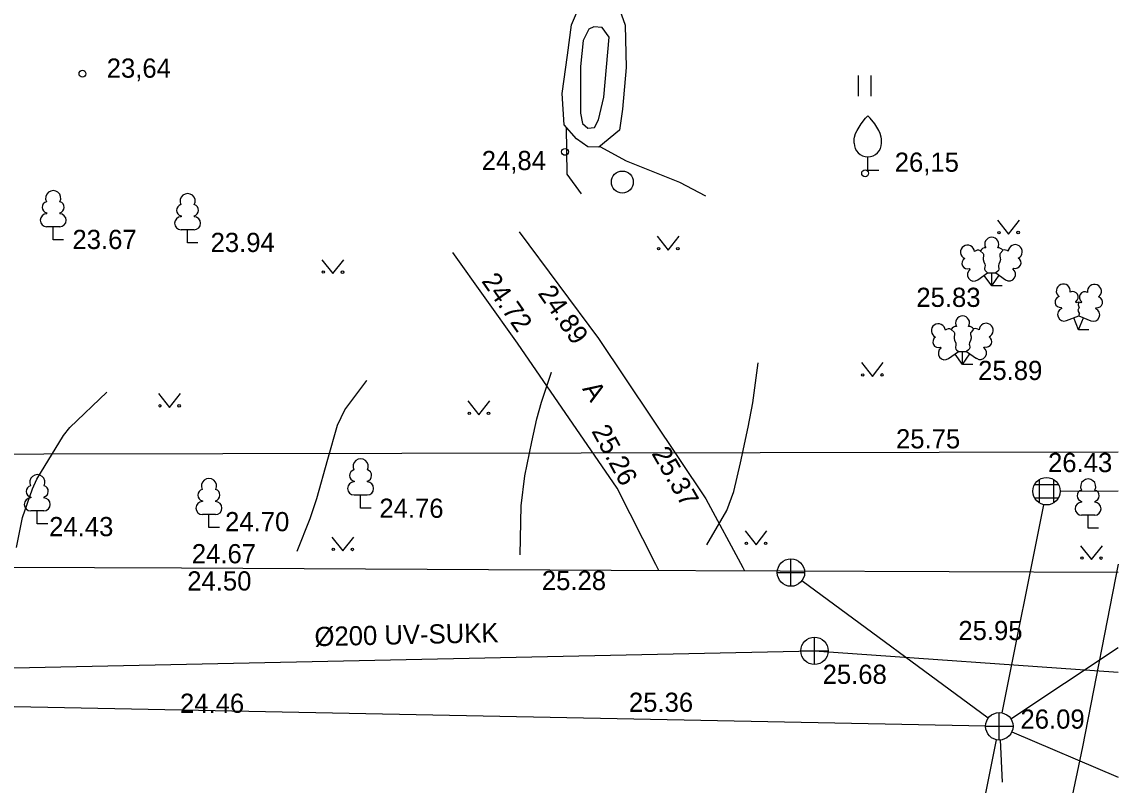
# Model space of a CAD drawing. Extents: x 714391 to 714584, y 6589993 to 6590151.
# Drawn here: x 714543.92 to 714583.92, y 6590093.39 to 6590121.23 of the extents above; entities that cross this region are included whole.
import ezdxf

# ---------------------------------------------------------------- set-up
doc = ezdxf.new("R2010")
doc.units = 0
for name, color, linetype in [('DKAEV', 7, 'Continuous'), ('HALJASTUS', 7, 'Continuous'), ('HOONE', 7, 'Continuous'), ('HORISONTAAL', 7, 'Continuous'), ('KKAEV', 7, 'Continuous'), ('KORGUS', 7, 'Continuous'), ('KTRASS', 7, 'Continuous'), ('PUU', 7, 'Continuous'), ('RELJEEF', 7, 'Continuous'), ('SKTRASS', 7, 'Continuous'), ('TEE', 7, 'Continuous'), ('TTRASS', 7, 'Continuous'), ('VTRASS', 7, 'Continuous')]:
    doc.layers.add(name, color=color, linetype=linetype)

msp = doc.modelspace()

# ---------------------------------------------------------------- linework, layer by layer
at = {"layer": 'DKAEV'}
for p, q in [((714581.058, 6590103.678), (714581.058, 6590104.544)), ((714581.558, 6590104.544), (714581.558, 6590103.678)), ((714580.875, 6590104.361), (714581.741, 6590104.361)), ((714581.741, 6590103.861), (714580.875, 6590103.861))]:
    msp.add_line(p, q, dxfattribs=at)
msp.add_circle((714581.308, 6590104.111), 0.5, dxfattribs=at)
at = {"layer": 'HALJASTUS'}
for p, q in [((714574.442, 6590119.281), (714574.442, 6590118.519)), ((714574.898, 6590119.281), (714574.898, 6590118.519)), ((714579.52, 6590113.998), (714579.925, 6590113.493)), ((714579.925, 6590113.493), (714580.32, 6590113.998)), ((714567.103, 6590113.411), (714567.508, 6590112.906)), ((714567.508, 6590112.906), (714567.903, 6590113.411)), ((714554.867, 6590112.553), (714555.272, 6590112.048)), ((714555.272, 6590112.048), (714555.667, 6590112.553)), ((714574.554, 6590108.805), (714574.959, 6590108.3)), ((714574.959, 6590108.3), (714575.354, 6590108.805)), ((714548.906, 6590107.676), (714549.311, 6590107.171)), ((714549.311, 6590107.171), (714549.706, 6590107.676)), ((714560.195, 6590107.406), (714560.6, 6590106.901)), ((714560.6, 6590106.901), (714560.995, 6590107.406)), ((714570.309, 6590102.664), (714570.714, 6590102.159)), ((714570.714, 6590102.159), (714571.109, 6590102.664)), ((714555.228, 6590102.439), (714555.633, 6590101.934)), ((714555.633, 6590101.934), (714556.028, 6590102.439)), ((714582.546, 6590102.123), (714582.951, 6590101.618)), ((714582.951, 6590101.618), (714583.346, 6590102.123))]:
    msp.add_line(p, q, dxfattribs=at)
for points in [[(714565.67, 6590121.87), (714565.94, 6590121.11), (714565.97, 6590119.57), (714565.84, 6590118.05), (714565.73, 6590117.28), (714564.97, 6590116.66), (714564.57, 6590116.68), (714564.16, 6590116.97), (714563.71, 6590117.48), (714563.64, 6590118.62), (714563.83, 6590120.02), (714563.98, 6590121.12), (714564.29, 6590121.86)], [(714564.343, 6590114.958), (714563.82, 6590115.68), (714563.79, 6590117.39)], [(714565.01, 6590116.69), (714565.97, 6590116.16), (714567.92, 6590115.39), (714568.862, 6590114.892)]]:
    msp.add_lwpolyline(points, dxfattribs=at)
for centre, radius in [((714565.83, 6590115.39), 0.4), ((714579.572, 6590113.548), 0.0428), ((714580.272, 6590113.548), 0.0452), ((714567.155, 6590112.961), 0.0428), ((714567.855, 6590112.961), 0.0452), ((714554.919, 6590112.103), 0.0428), ((714555.619, 6590112.103), 0.0452), ((714574.606, 6590108.356), 0.0428), ((714575.306, 6590108.356), 0.0452), ((714548.958, 6590107.227), 0.0428), ((714549.658, 6590107.227), 0.0452), ((714560.247, 6590106.956), 0.0428), ((714560.947, 6590106.956), 0.0452), ((714570.361, 6590102.215), 0.0428), ((714571.061, 6590102.215), 0.0452), ((714555.28, 6590101.989), 0.0428), ((714555.98, 6590101.989), 0.0452), ((714582.598, 6590101.673), 0.0428), ((714583.298, 6590101.673), 0.0452)]:
    msp.add_circle(centre, radius, dxfattribs=at)
at = {"layer": 'HOONE'}
for p, q in [((714581.808, 6590104.114), (714583.92, 6590104.125)), ((714579.685, 6590096.028), (714581.21, 6590103.621)), ((714580.047, 6590095.341), (714583.92, 6590093.681))]:
    msp.add_line(p, q, dxfattribs=at)
at = {"layer": 'HORISONTAAL'}
for points in [[(714568.917, 6590102.154), (714569.639, 6590103.411), (714569.639, 6590103.411), (714569.895, 6590104.108), (714569.895, 6590104.108), (714570.14, 6590105.146), (714570.14, 6590105.146), (714570.427, 6590106.452), (714570.427, 6590106.452), (714570.591, 6590107.34), (714570.591, 6590107.34), (714570.791, 6590108.791), (714570.791, 6590108.791)], [(714553.968, 6590101.924), (714554.438, 6590103.119), (714554.438, 6590103.119), (714554.685, 6590103.847), (714554.685, 6590103.847), (714555.084, 6590105.277), (714555.084, 6590105.277), (714555.435, 6590106.518), (714555.435, 6590106.518), (714555.701, 6590107.079), (714555.701, 6590107.079), (714556.507, 6590108.153), (714556.507, 6590108.153)], [(714562.098, 6590101.794), (714562.135, 6590103.58), (714562.135, 6590103.58), (714562.278, 6590104.674), (714562.278, 6590104.674), (714562.533, 6590105.919), (714562.533, 6590105.919), (714562.715, 6590106.756), (714562.715, 6590106.756), (714562.877, 6590107.355), (714562.877, 6590107.355), (714563.251, 6590108.454), (714563.251, 6590108.454)], [(714543.72, 6590102.062), (714543.949, 6590103.152), (714543.949, 6590103.152), (714544.314, 6590104.204), (714544.314, 6590104.204), (714544.467, 6590104.547), (714545.44, 6590106.141), (714545.44, 6590106.141), (714545.675, 6590106.435), (714547.022, 6590107.729), (714547.022, 6590107.729)]]:
    msp.add_lwpolyline(points, dxfattribs=at)
at = {"layer": 'KKAEV'}
for p, q in [((714571.984, 6590100.645), (714571.984, 6590101.645)), ((714571.484, 6590101.145), (714572.484, 6590101.145)), ((714572.844, 6590097.791), (714572.844, 6590098.791)), ((714572.344, 6590098.291), (714573.344, 6590098.291)), ((714579.587, 6590095.038), (714579.587, 6590096.038)), ((714579.087, 6590095.538), (714580.087, 6590095.538))]:
    msp.add_line(p, q, dxfattribs=at)
for centre in [(714571.984, 6590101.145), (714572.844, 6590098.291), (714579.587, 6590095.538)]:
    msp.add_circle(centre, 0.5, dxfattribs=at)
at = {"layer": 'KORGUS'}
for centre in [(714546.13, 6590119.34), (714563.74, 6590116.49), (714574.69, 6590115.71)]:
    msp.add_circle(centre, 0.125, dxfattribs=at)
at = {"layer": 'KTRASS'}
msp.add_lwpolyline([(714540.177, 6590097.597), (714572.844, 6590098.291), (714583.92, 6590097.517)], dxfattribs=at)
at = {"layer": 'PUU'}
for p, q in [((714574.79, 6590115.81), (714574.79, 6590116.31)), ((714575.19, 6590115.81), (714574.79, 6590115.81)), ((714544.823, 6590114.261), (714544.823, 6590114.231)), ((714545.303, 6590114.261), (714545.303, 6590114.231)), ((714549.727, 6590114.152), (714549.727, 6590114.122)), ((714550.207, 6590114.152), (714550.207, 6590114.122)), ((714545.303, 6590113.756), (714544.823, 6590113.756)), ((714545.063, 6590113.281), (714545.063, 6590113.756)), ((714545.443, 6590113.281), (714545.063, 6590113.281)), ((714550.207, 6590113.647), (714549.727, 6590113.647)), ((714549.967, 6590113.172), (714549.967, 6590113.647)), ((714550.347, 6590113.172), (714549.967, 6590113.172)), ((714578.524, 6590112.203), (714578.499, 6590112.238)), ((714578.799, 6590111.818), (714579.159, 6590112.073)), ((714579.159, 6590112.073), (714579.454, 6590112.073)), ((714579.309, 6590111.598), (714579.309, 6590112.073)), ((714579.454, 6590112.073), (714579.814, 6590111.828)), ((714580.084, 6590112.218), (714580.104, 6590112.253)), ((714579.309, 6590111.598), (714579.034, 6590111.983)), ((714579.309, 6590111.598), (714579.579, 6590111.988)), ((714579.689, 6590111.598), (714579.309, 6590111.598)), ((714582.393, 6590110.989), (714582.378, 6590111.024)), ((714582.578, 6590110.984), (714582.593, 6590111.024)), ((714581.863, 6590110.779), (714581.848, 6590110.819)), ((714582.038, 6590110.334), (714582.483, 6590110.509)), ((714582.483, 6590110.509), (714582.923, 6590110.329)), ((714583.103, 6590110.769), (714583.118, 6590110.809)), ((714582.478, 6590109.999), (714582.303, 6590110.439)), ((714582.478, 6590109.999), (714582.658, 6590110.439)), ((714582.858, 6590109.999), (714582.478, 6590109.999)), ((714577.46, 6590109.334), (714577.435, 6590109.369)), ((714579.02, 6590109.349), (714579.04, 6590109.384)), ((714577.735, 6590108.949), (714578.095, 6590109.204)), ((714578.245, 6590108.729), (714577.97, 6590109.114)), ((714578.095, 6590109.204), (714578.39, 6590109.204)), ((714578.245, 6590108.729), (714578.245, 6590109.204)), ((714578.245, 6590108.729), (714578.515, 6590109.119)), ((714578.39, 6590109.204), (714578.75, 6590108.959)), ((714578.625, 6590108.729), (714578.245, 6590108.729)), ((714556.042, 6590104.479), (714556.042, 6590104.449)), ((714556.522, 6590104.479), (714556.522, 6590104.449)), ((714544.243, 6590103.9), (714544.243, 6590103.87)), ((714544.723, 6590103.9), (714544.723, 6590103.87)), ((714550.506, 6590103.764), (714550.506, 6590103.734)), ((714550.986, 6590103.764), (714550.986, 6590103.734)), ((714556.522, 6590103.974), (714556.042, 6590103.974)), ((714556.282, 6590103.499), (714556.282, 6590103.974)), ((714582.589, 6590103.742), (714582.589, 6590103.712)), ((714583.069, 6590103.742), (714583.069, 6590103.712)), ((714544.723, 6590103.395), (714544.243, 6590103.395)), ((714544.483, 6590102.92), (714544.483, 6590103.395)), ((714556.662, 6590103.499), (714556.282, 6590103.499)), ((714544.863, 6590102.92), (714544.483, 6590102.92)), ((714550.986, 6590103.259), (714550.506, 6590103.259)), ((714550.746, 6590102.784), (714550.746, 6590103.259)), ((714583.069, 6590103.237), (714582.589, 6590103.237)), ((714582.829, 6590102.762), (714582.829, 6590103.237)), ((714551.126, 6590102.784), (714550.746, 6590102.784)), ((714583.209, 6590102.762), (714582.829, 6590102.762))]:
    msp.add_line(p, q, dxfattribs=at)
for points in [[(714574.29, 6590116.81), (714574.29, 6590116.96), (714574.3, 6590117.025), (714574.335, 6590117.155), (714574.395, 6590117.275), (714574.54, 6590117.51), (714574.7, 6590117.715), (714574.79, 6590117.81)], [(714575.29, 6590116.81), (714575.29, 6590116.96), (714575.28, 6590117.025), (714575.245, 6590117.155), (714575.185, 6590117.275), (714575.04, 6590117.51), (714574.88, 6590117.715), (714574.79, 6590117.81)], [(714578.894, 6590112.883), (714578.999, 6590112.783), (714579.014, 6590112.753), (714579.014, 6590112.698), (714578.999, 6590112.608), (714578.999, 6590112.563), (714579.019, 6590112.483), (714579.059, 6590112.393), (714579.069, 6590112.348), (714579.064, 6590112.303), (714579.049, 6590112.238), (714579.049, 6590112.208), (714579.069, 6590112.168), (714579.094, 6590112.138), (714579.159, 6590112.073)], [(714579.714, 6590112.898), (714579.619, 6590112.783), (714579.604, 6590112.753), (714579.604, 6590112.698), (714579.619, 6590112.608), (714579.624, 6590112.563), (714579.604, 6590112.483), (714579.564, 6590112.393), (714579.554, 6590112.348), (714579.559, 6590112.303), (714579.574, 6590112.238), (714579.574, 6590112.208), (714579.554, 6590112.168), (714579.529, 6590112.138), (714579.459, 6590112.073)], [(714582.483, 6590111.004), (714582.463, 6590110.929), (714582.463, 6590110.909), (714582.473, 6590110.879), (714582.493, 6590110.844), (714582.498, 6590110.824), (714582.483, 6590110.789), (714582.458, 6590110.739), (714582.453, 6590110.714), (714582.458, 6590110.699), (714582.468, 6590110.669), (714582.503, 6590110.609), (714582.508, 6590110.589), (714582.503, 6590110.569), (714582.488, 6590110.534), (714582.483, 6590110.509)], [(714577.83, 6590110.014), (714577.935, 6590109.914), (714577.95, 6590109.884), (714577.95, 6590109.829), (714577.935, 6590109.739), (714577.935, 6590109.694), (714577.955, 6590109.614), (714577.995, 6590109.524), (714578.005, 6590109.479), (714578, 6590109.434), (714577.985, 6590109.369), (714577.985, 6590109.339), (714578.005, 6590109.299), (714578.03, 6590109.269), (714578.095, 6590109.204)], [(714578.65, 6590110.029), (714578.555, 6590109.914), (714578.54, 6590109.884), (714578.54, 6590109.829), (714578.555, 6590109.739), (714578.56, 6590109.694), (714578.54, 6590109.614), (714578.5, 6590109.524), (714578.49, 6590109.479), (714578.495, 6590109.434), (714578.51, 6590109.369), (714578.51, 6590109.339), (714578.49, 6590109.299), (714578.465, 6590109.269), (714578.395, 6590109.204)]]:
    msp.add_lwpolyline(points, dxfattribs=at)
for centre, radius, start, end in [((714574.79, 6590116.81), 0.5, 180, 0), ((714545.063, 6590114.801), 0.277, 332.5799, 207.4201), ((714549.967, 6590114.692), 0.277, 332.5799, 207.4201), ((714544.873, 6590114.469), 0.212, 105.2441, 257.079), ((714545.253, 6590114.469), 0.212, 282.921, 74.7559), ((714549.777, 6590114.36), 0.212, 105.2441, 257.079), ((714550.157, 6590114.36), 0.212, 282.921, 74.7559), ((714544.826, 6590113.994), 0.237, 90, 270), ((714545.301, 6590113.994), 0.237, 270, 90), ((714549.729, 6590113.885), 0.237, 90, 270), ((714550.204, 6590113.885), 0.237, 270, 90), ((714579.309, 6590113.118), 0.256, 90.0013, 211.0159), ((714579.309, 6590113.118), 0.256, 328.9841, 89.9987), ((714578.426, 6590112.835), 0.256, 125.5389, 246.5536), ((714578.426, 6590112.835), 0.256, 4.5218, 125.5364), ((714578.812, 6590112.702), 0.202, 65.2382, 130.7412), ((714579.071, 6590112.786), 0.202, 84.7965, 150.2995), ((714579.546, 6590112.786), 0.202, 34.3857, 95.2035), ((714579.785, 6590112.711), 0.202, 50.3173, 111.1351), ((714580.169, 6590112.851), 0.256, 55.522, 176.5367), ((714580.169, 6590112.851), 0.256, 294.5049, 55.5195), ((714578.426, 6590112.426), 0.202, 120.3342, 291.9047), ((714580.177, 6590112.442), 0.202, 249.1538, 60.7243), ((714578.663, 6590112.012), 0.237, 125.5377, 305.5366), ((714579.947, 6590112.024), 0.237, 235.5219, 55.5208), ((714581.921, 6590111.413), 0.256, 350.4856, 111.5002), ((714581.921, 6590111.413), 0.256, 111.5027, 232.5173), ((714582.264, 6590111.191), 0.202, 305.1345, 116.705), ((714582.711, 6590111.187), 0.202, 62.412, 233.9825), ((714583.057, 6590111.404), 0.256, 67.6168, 188.6314), ((714583.057, 6590111.404), 0.256, 306.5997, 67.6143), ((714581.822, 6590111.017), 0.202, 106.2979, 277.8684), ((714582.482, 6590110.766), 0.237, 66.7655, 111.5015), ((714583.15, 6590111.007), 0.202, 261.2486, 72.8191), ((714578.245, 6590110.249), 0.256, 90.0013, 211.0159), ((714578.245, 6590110.249), 0.256, 328.9841, 89.9987), ((714581.952, 6590110.557), 0.237, 111.5014, 291.5004), ((714583.013, 6590110.549), 0.237, 247.6166, 67.6155), ((714577.362, 6590109.966), 0.256, 125.5389, 246.5536), ((714577.362, 6590109.966), 0.256, 4.5218, 125.5364), ((714578.007, 6590109.917), 0.202, 84.7965, 150.2995), ((714578.482, 6590109.917), 0.202, 34.3857, 95.2035), ((714579.105, 6590109.982), 0.256, 55.522, 176.5367), ((714579.105, 6590109.982), 0.256, 294.5049, 55.5195), ((714577.362, 6590109.557), 0.202, 120.3342, 291.9047), ((714577.748, 6590109.833), 0.202, 65.2382, 130.7412), ((714578.721, 6590109.842), 0.202, 50.3173, 111.1351), ((714579.113, 6590109.573), 0.202, 249.1538, 60.7243), ((714577.599, 6590109.143), 0.237, 125.5377, 305.5366), ((714578.883, 6590109.155), 0.237, 235.5219, 55.5208), ((714556.282, 6590105.019), 0.277, 332.5799, 207.4201), ((714556.092, 6590104.687), 0.212, 105.2441, 257.079), ((714556.472, 6590104.687), 0.212, 282.921, 74.7559), ((714544.483, 6590104.44), 0.277, 332.5799, 207.4201), ((714550.746, 6590104.304), 0.277, 332.5799, 207.4201), ((714582.829, 6590104.282), 0.277, 332.5799, 207.4201), ((714544.293, 6590104.107), 0.212, 105.2441, 257.079), ((714544.673, 6590104.107), 0.212, 282.921, 74.7559), ((714550.556, 6590103.971), 0.212, 105.2441, 257.079), ((714550.936, 6590103.971), 0.212, 282.921, 74.7559), ((714556.044, 6590104.212), 0.237, 90, 270), ((714556.519, 6590104.212), 0.237, 270, 90), ((714582.639, 6590103.95), 0.212, 105.2441, 257.079), ((714583.019, 6590103.95), 0.212, 282.921, 74.7559), ((714544.245, 6590103.633), 0.237, 90, 270), ((714544.72, 6590103.633), 0.237, 270, 90), ((714550.508, 6590103.497), 0.237, 90, 270), ((714550.983, 6590103.497), 0.237, 270, 90), ((714582.591, 6590103.475), 0.237, 90, 270), ((714583.066, 6590103.475), 0.237, 270, 90)]:
    msp.add_arc(centre, radius, start, end, dxfattribs=at)
at = {"layer": 'RELJEEF'}
for points in [[(714564.61, 6590120.96), (714564.4, 6590120.55)], [(714564.79, 6590121.05), (714564.61, 6590120.96)], [(714565.09, 6590121.03), (714564.79, 6590121.05)], [(714565.35, 6590120.68), (714565.09, 6590121.03)], [(714564.4, 6590120.55), (714564.31, 6590119.6)], [(714565.15, 6590118.48), (714565.35, 6590120.68)], [(714564.31, 6590119.6), (714564.31, 6590117.9)], [(714564.96, 6590117.66), (714565.15, 6590118.48)], [(714564.31, 6590117.9), (714564.38, 6590117.53)], [(714564.38, 6590117.53), (714564.57, 6590117.36)], [(714564.57, 6590117.36), (714564.81, 6590117.38)], [(714564.81, 6590117.38), (714564.96, 6590117.66)]]:
    msp.add_lwpolyline(points, dxfattribs=at)
at = {"layer": 'SKTRASS'}
for p, q in [((714579.185, 6590095.835), (714572.386, 6590100.848)), ((714580.004, 6590095.814), (714583.92, 6590098.41)), ((714579.087, 6590095.548), (714532.128, 6590096.473)), ((714573.957, 6590067.525), (714579.488, 6590095.048)), ((714579.613, 6590095.039), (714579.694, 6590093.503))]:
    msp.add_line(p, q, dxfattribs=at)
at = {"layer": 'TEE'}
for points in [[(714583.92, 6590101.143), (714565.419, 6590101.225), (714549.748, 6590101.3), (714530.696, 6590101.382), (714516.957, 6590101.382), (714497.906, 6590101.442), (714488.527, 6590101.467), (714476.238, 6590101.479), (714465.964, 6590101.492), (714465.149, 6590101.593), (714461.989, 6590102.308), (714461.271, 6590102.628), (714460.534, 6590103.105), (714459.97, 6590103.737), (714459.406, 6590104.596), (714458.782, 6590106.528), (714458.59, 6590109.02), (714468.756, 6590132.53), (714474.437, 6590144.828), (714474.939, 6590145.152), (714475.17, 6590145.792), (714474.999, 6590146.077), (714477.095, 6590151.075)], [(714562.072, 6590113.578), (714564.957, 6590109.681), (714568.878, 6590103.836), (714570.223, 6590101.333), (714570.293, 6590101.203)], [(714567.168, 6590101.217), (714567.056, 6590101.438), (714565.643, 6590104.218), (714562.001, 6590109.513), (714559.652, 6590112.816)]]:
    msp.add_lwpolyline(points, dxfattribs=at)
at = {"layer": 'TTRASS'}
msp.add_lwpolyline([(714583.92, 6590105.531), (714538.176, 6590105.447)], dxfattribs=at)
at = {"layer": 'VTRASS'}
msp.add_lwpolyline([(714583.92, 6590101.451), (714582.627, 6590094.792), (714580.583, 6590085.094), (714578.759, 6590074.872), (714576.646, 6590066.323), (714576.499, 6590065.948), (714576.768, 6590065.956), (714576.95, 6590065.889)], dxfattribs=at)

# ---------------------------------------------------------------- texts
at = {"layer": 'KORGUS'}
for s, p in [('23,64', (714547.016, 6590119.195)), ('24,84', (714560.701, 6590115.825)), ('26,15', (714575.771, 6590115.765)), ('23.67', (714545.767, 6590112.947)), ('23.94', (714550.807, 6590112.838)), ('25.83', (714576.559, 6590110.835)), ('25.89', (714578.814, 6590108.169)), ('25.75', (714575.817, 6590105.675)), ('26.43', (714581.365, 6590104.809)), ('24.76', (714556.964, 6590103.142)), ('24.70', (714551.337, 6590102.653)), ('24.43', (714544.916, 6590102.473)), ('24.67', (714550.123, 6590101.484)), ('24.50', (714549.955, 6590100.491)), ('25.28', (714562.895, 6590100.507)), ('25.95', (714578.093, 6590098.682)), ('25.68', (714573.139, 6590097.086)), ('24.46', (714549.69, 6590096.029)), ('25.36', (714566.071, 6590096.065)), ('26.09', (714580.359, 6590095.452))]:
    msp.add_text(s, height=0.7, dxfattribs=at).set_placement(p)
for s, rotation, p in [('24.72', 304.9393, (714560.672, 6590111.775)), ('24.89', 304.6057, (714562.727, 6590111.331)), ('25.26', 298.3499, (714564.691, 6590106.31)), ('25.37', 300.0271, (714566.882, 6590105.491))]:
    msp.add_text(s, height=0.7, rotation=rotation, dxfattribs=at).set_placement(p)
at = {"layer": 'KTRASS'}
msp.add_text('%%c200 UV-SUKK', height=0.7, rotation=1.2633, dxfattribs=at).set_placement((714554.606, 6590098.459))
at = {"layer": 'TEE'}
msp.add_text('A', height=0.7, rotation=302.6806, dxfattribs=at).set_placement((714564.352, 6590107.845))

doc.saveas('drawing.dxf')
